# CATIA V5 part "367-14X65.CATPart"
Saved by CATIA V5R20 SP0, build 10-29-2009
Part number: 367-14X65
Definition: NONE
Nomenclature: 367-14X65
Source: Unknown
Description: 367-14X65
Bounding box of the stored display mesh (mm): x 0 to 65, y -14 to 14, z -14 to 14
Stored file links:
  C:\Users\Utente\Desktop\IO LAVORO\3D X SITO CF\X SITO\PLASTICA\3D files 367\367-14X65.CATPart
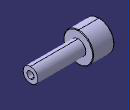
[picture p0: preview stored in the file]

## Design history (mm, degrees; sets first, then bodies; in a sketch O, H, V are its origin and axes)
Body1 "367-14X65" (main body)
  Solid1: solid without history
